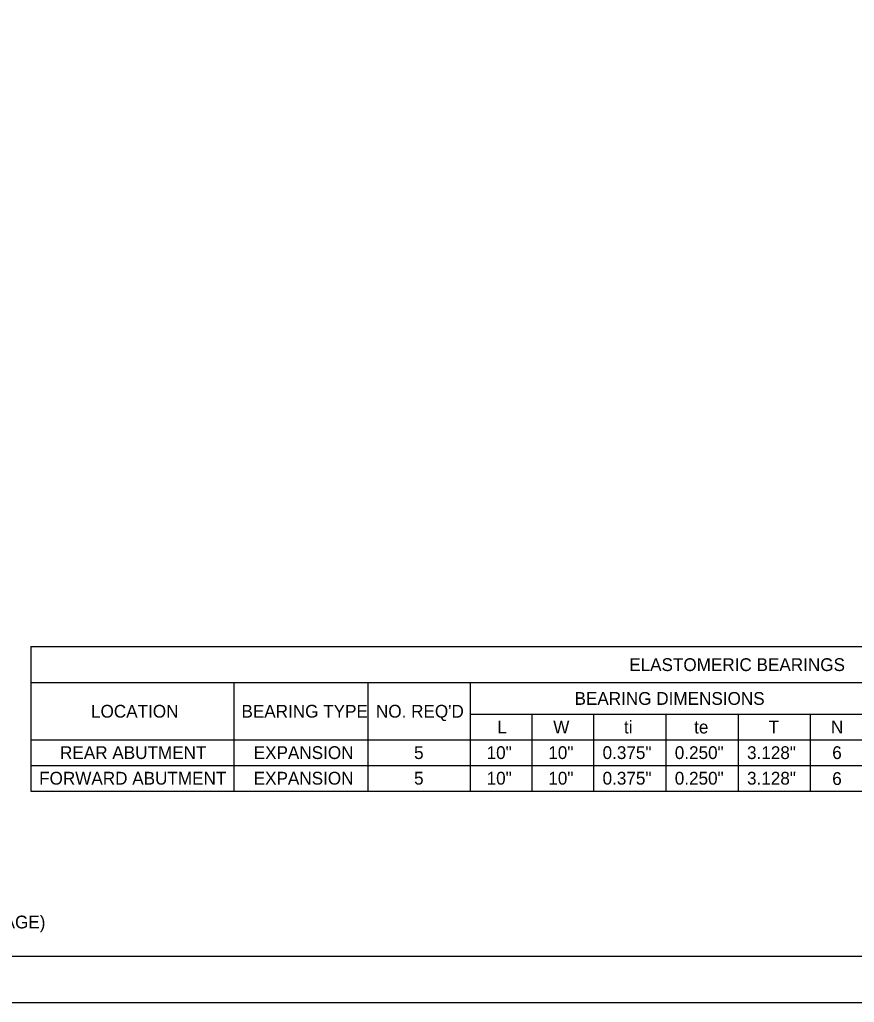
# Model space of a CAD drawing. Extents: x 0 to 34, y 0 to 22.
# Drawn here: x 15.82 to 24.96, y 0 to 10.76 of the extents above; entities that cross this region are included whole.
import ezdxf

# ---------------------------------------------------------------- set-up
doc = ezdxf.new("R2010")
doc.units = 0
for name, color, linetype in [('SH_Border', 7, 'Continuous'), ('SH_Cut_Line', 7, 'Continuous'), ('SH_Text', 7, 'Continuous')]:
    doc.layers.add(name, color=color, linetype=linetype)

msp = doc.modelspace()

# ---------------------------------------------------------------- linework, layer by layer
at = {"layer": 'SH_Border'}
msp.add_lwpolyline([(1.5, 21.5), (33.5, 21.5), (33.5, 0.5), (1.5, 0.5)], close=True, dxfattribs=at)
at = {"layer": 'SH_Cut_Line'}
msp.add_lwpolyline([(0, 0), (34, 0), (34, 22), (0, 22)], close=True, dxfattribs=at)
at = {"layer": 'SH_Text'}
for p, q in [((15.944, 3.894), (31.261, 3.894)), ((15.944, 3.894), (15.944, 2.313)), ((15.944, 3.499), (31.261, 3.499)), ((18.167, 3.499), (18.167, 2.313)), ((19.633, 3.499), (19.633, 2.313)), ((20.753, 3.499), (20.753, 2.313)), ((20.753, 3.153), (29.433, 3.153)), ((21.428, 3.153), (21.428, 2.313)), ((22.103, 3.153), (22.103, 2.313)), ((22.894, 3.153), (22.894, 2.313)), ((23.685, 3.153), (23.685, 2.313)), ((24.475, 3.153), (24.475, 2.313)), ((15.944, 2.873), (31.261, 2.873)), ((15.944, 2.593), (31.261, 2.593)), ((15.944, 2.313), (31.261, 2.313))]:
    msp.add_line(p, q, dxfattribs=at)

# ---------------------------------------------------------------- texts
for s, p in [('ELASTOMERIC BEARINGS', (22.493, 3.626)), ('BEARING DIMENSIONS', (21.895, 3.256)), ('LOCATION', (16.604, 3.116)), ('BEARING TYPE', (18.25, 3.116)), ("NO. REQ'D", (19.722, 3.116)), ('L', (21.049, 2.943)), ('W', (21.662, 2.943)), ('ti', (22.436, 2.943)), ('te', (23.204, 2.943)), ('T', (24.018, 2.943)), ('N', (24.701, 2.943)), ('REAR ABUTMENT', (16.265, 2.663)), ('EXPANSION', (18.384, 2.663)), ('5', (20.139, 2.663)), ('10"', (20.933, 2.663)), ('10"', (21.608, 2.663)), ('0.375"', (22.202, 2.663)), ('0.250"', (22.992, 2.663)), ('3.128"', (23.783, 2.663)), ('6', (24.715, 2.663)), ('FORWARD ABUTMENT', (16.036, 2.383)), ('EXPANSION', (18.384, 2.383)), ('5', (20.139, 2.383)), ('10"', (20.933, 2.383)), ('10"', (21.608, 2.383)), ('0.375"', (22.202, 2.383)), ('0.250"', (22.992, 2.383)), ('3.128"', (23.783, 2.383)), ('6', (24.715, 2.379)), ('INTERNAL STEEL LAMINATE THICKNESS = 0.1046" (12 GAGE)', (10.592, 0.809))]:
    msp.add_text(s, height=0.14, dxfattribs=at).set_placement(p)

doc.saveas('drawing.dxf')
